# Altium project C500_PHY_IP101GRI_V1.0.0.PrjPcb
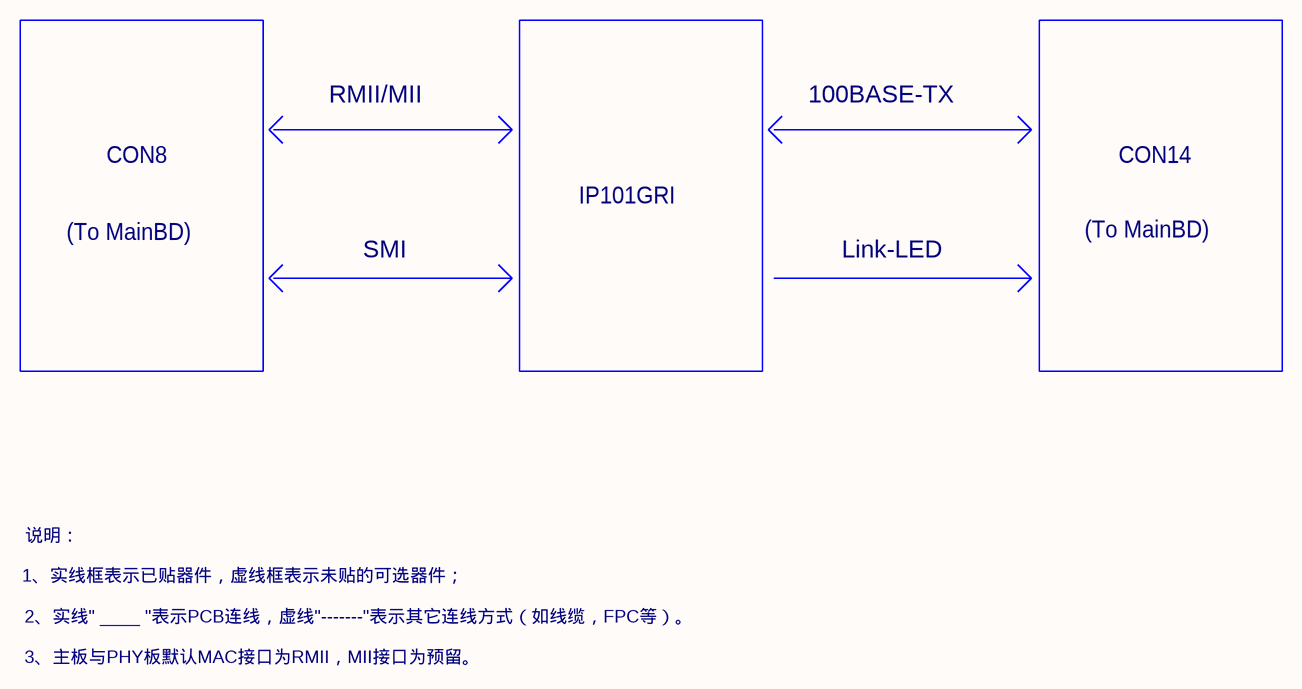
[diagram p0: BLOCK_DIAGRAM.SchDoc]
3 sheets, 70 parts. Net scope: flat (ports and power ports of the same name join across sheets).
Sheets:
  BLOCK_DIAGRAM.SchDoc
  INTERFACE.SchDoc
  IP101GRI.SchDoc

## Sheet BLOCK_DIAGRAM.SchDoc: C500_PHY_IP101GRI_PHY
size A3; Revision: V1.0.0; SheetNumber: 1; SheetTotal: 3; Release Date: 2019-05-28; SchModifyDate: 2019/5/28; PCBVersion: V1.0.0; PCBPartNumber: C500_PHY_IP101GRI_V1.0.0

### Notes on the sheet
- RMII/MII
- 100BASE-TX
- CON8
- CON14
- (To MainBD)
- SMI
- IP101GRI
- Link-LED
- 1、实线框表示已贴器件，虚线框表示未贴的可选器件；
- 说明：
- 2、实线" ____ "表示PCB连线，虚线"-------"表示其它连线方式（如线缆，FPC等）。
- 3、主板与PHY板默认MAC接口为RMII，MII接口为预留。

## Sheet INTERFACE.SchDoc: C500_PHY_IP101GRI_PHY
size A3; Revision: V1.0.0; SheetNumber: 2; SheetTotal: 3; Release Date: 2019-05-28; SchModifyDate: 2019/5/28; PCBVersion: V1.0.0; PCBPartNumber: C500_PHY_IP101GRI_V1.0.0
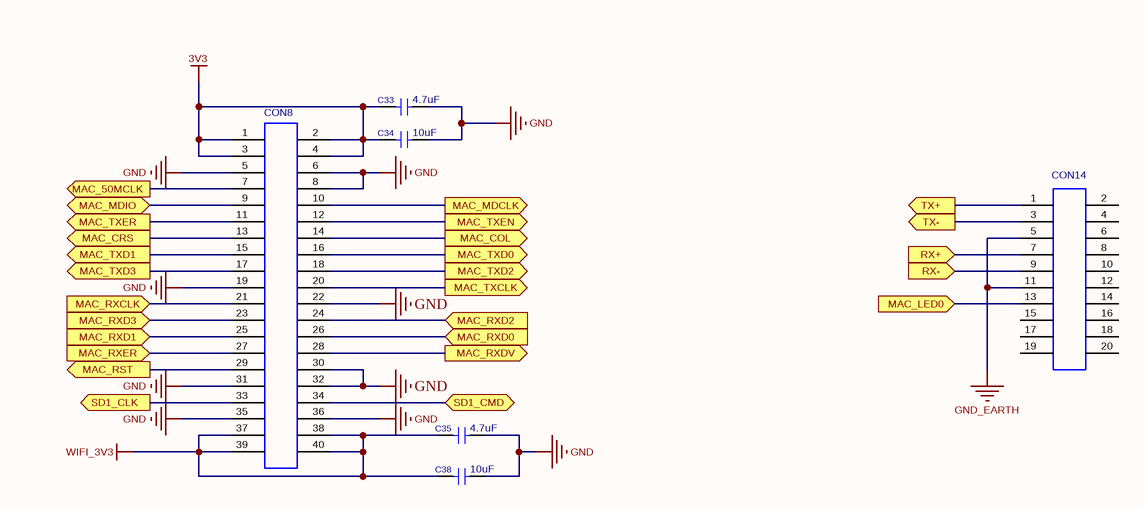
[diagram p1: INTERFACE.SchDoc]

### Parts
C33  4.7uF  [C0603]
C34  10uF  [C0805]
C35  4.7uF  [C0603]
C38  10uF  [C0805]
CON8  CON20X2_0MM5_BTB_DF12  [CON20X2_0MM5_BTB_DF12_N]  (value not drawn)
CON14  CON10X2_0MM5_BTB_DF12  [CON10X2_0MM5_BTB_DF12_N]  (value not drawn)

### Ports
MAC_50MCLK (out), MAC_COL (out), MAC_CRS (out), MAC_LED0 (in), MAC_MDCLK (out), MAC_MDIO (bidir), MAC_RST (out), MAC_RXCLK (in), MAC_RXD0 (in), MAC_RXD1 (in), MAC_RXD2 (in), MAC_RXD3 (in), MAC_RXDV (out), MAC_RXER (in), MAC_TXCLK (out), MAC_TXD0 (out), MAC_TXD1 (out), MAC_TXD2 (out), MAC_TXD3 (out), MAC_TXEN (out), MAC_TXER (out), RX+ (in), RX- (in), SD1_CLK (out), SD1_CMD (bidir), TX+ (out), TX- (out)

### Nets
3V3: C33.1 C34.1 CON8.1 CON8.2 CON8.3 CON8.4
GND: C33.2 C34.2 C35.2 C38.2 CON8.5 CON8.6 CON8.8 CON8.19 CON8.22 CON8.30 CON8.31 CON8.32 CON8.35 CON8.36
GND_EARTH: CON14.5 CON14.11
WIFI_3V3: C35.1 C38.1 CON8.37 CON8.38 CON8.39 CON8.40
MAC_50MCLK: CON8.7 ; port MAC_50MCLK
MAC_COL: CON8.14 ; port MAC_COL
MAC_CRS: CON8.13 ; port MAC_CRS
MAC_LED0: CON14.13 ; port MAC_LED0
MAC_MDCLK: CON8.10 ; port MAC_MDCLK
MAC_MDIO: CON8.9 ; port MAC_MDIO
MAC_RST: CON8.29 ; port MAC_RST
MAC_RXCLK: CON8.21 ; port MAC_RXCLK
MAC_RXD0: CON8.26 ; port MAC_RXD0
MAC_RXD1: CON8.25 ; port MAC_RXD1
MAC_RXD2: CON8.24 ; port MAC_RXD2
MAC_RXD3: CON8.23 ; port MAC_RXD3
MAC_RXDV: CON8.28 ; port MAC_RXDV
MAC_RXER: CON8.27 ; port MAC_RXER
MAC_TXCLK: CON8.20 ; port MAC_TXCLK
MAC_TXD0: CON8.16 ; port MAC_TXD0
MAC_TXD1: CON8.15 ; port MAC_TXD1
MAC_TXD2: CON8.18 ; port MAC_TXD2
MAC_TXD3: CON8.17 ; port MAC_TXD3
MAC_TXEN: CON8.12 ; port MAC_TXEN
RX+: CON14.7 ; port RX+
RX-: CON14.9 ; port RX-
TX+: CON14.1 ; port TX+
TX-: CON14.3 ; port TX-
NetCON8_11: CON8.11 ; port MAC_TXER
NetCON8_33: CON8.33 ; port SD1_CLK
NetCON8_34: CON8.34 ; port SD1_CMD

Not connected (* = marked no-connect by the designer): CON14 2 4 6 8 10 12 14 15 16 17 18 19 20

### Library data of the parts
C33 C35 = CC0304752XX: C/C,4.7uF,10V +/-10%,0603; Catalog: 陶瓷电容
C34 C38 = CC0501063XX: C/C,10uF,16V,+/-20%,0805; Catalog: 陶瓷电容
CON8 = CNBBM4000XX: 0.5mm ，BTB2*20Pin，SMT，公座，H3.0，DF12#(3.0)-40DS-0.5; PCB DECAL: CON20X2_0MM5_BTB_DF12_BOTTOM; Catalog: Connector
CON14 = CNBBM2000XX: 0.5mm ，BTB2*10Pin，SMT，公座，H3.0，DF12#(3.0)-20DS-0.5; PCB DECAL: CON10X2_0MM5_BTB_DF12_BOTTOM; Catalog: Connector

## Sheet IP101GRI.SchDoc: C500_PHY_IP101GRI_PHY
size A3; Revision: V1.0.0; SheetNumber: 3; SheetTotal: 3; Release Date: 2019-05-28; SchModifyDate: 2019/5/28; PCBVersion: V1.0.0; PCBPartNumber: C500_PHY_IP101GRI_V1.0.0
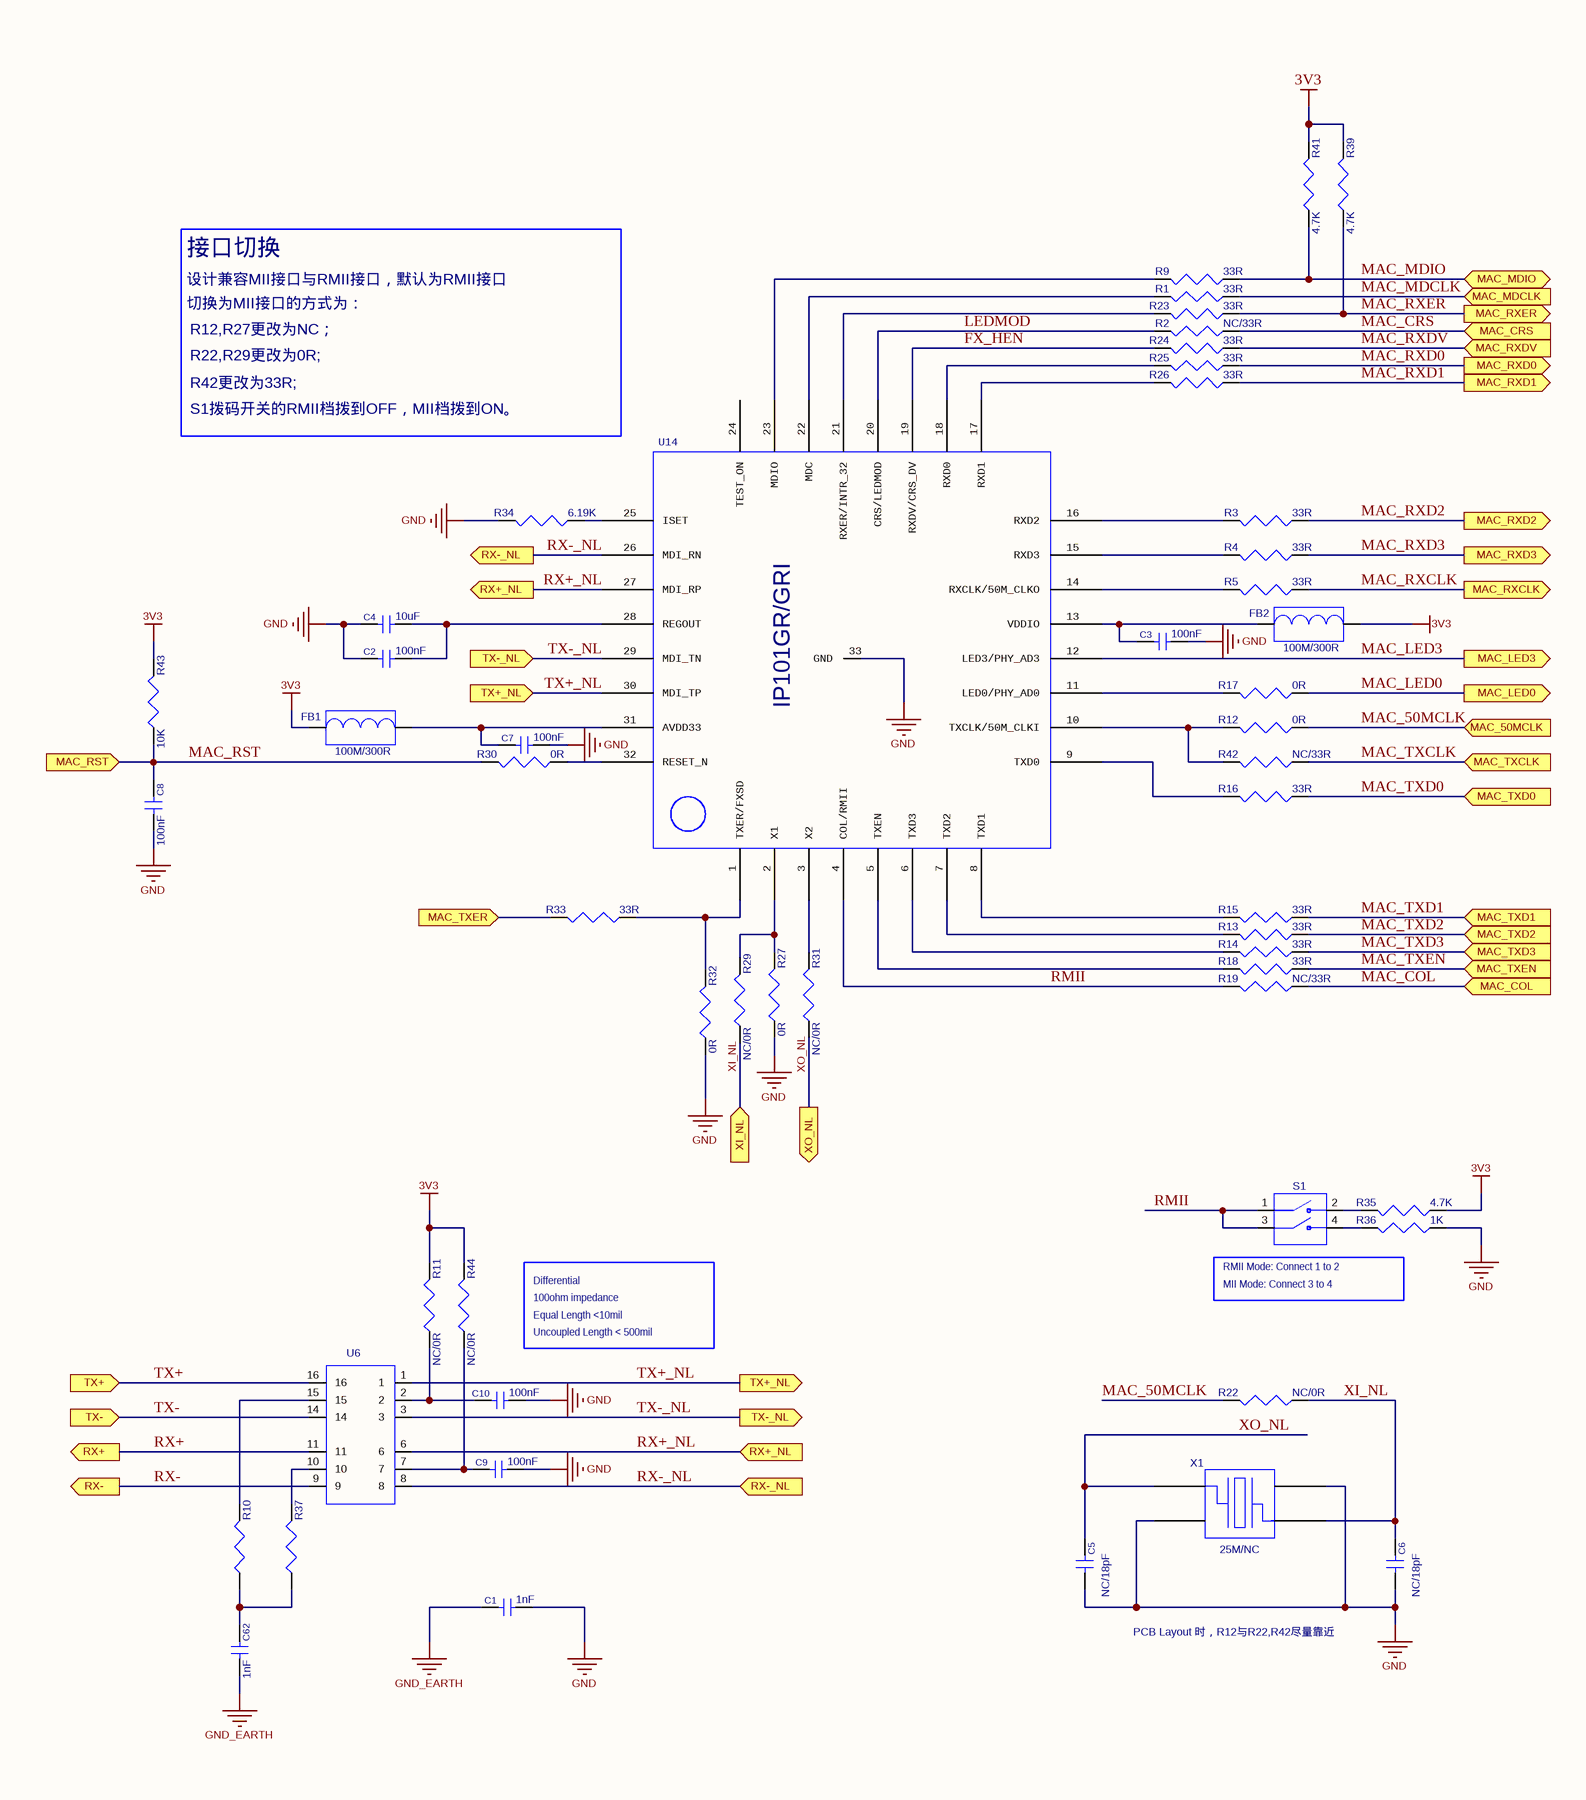
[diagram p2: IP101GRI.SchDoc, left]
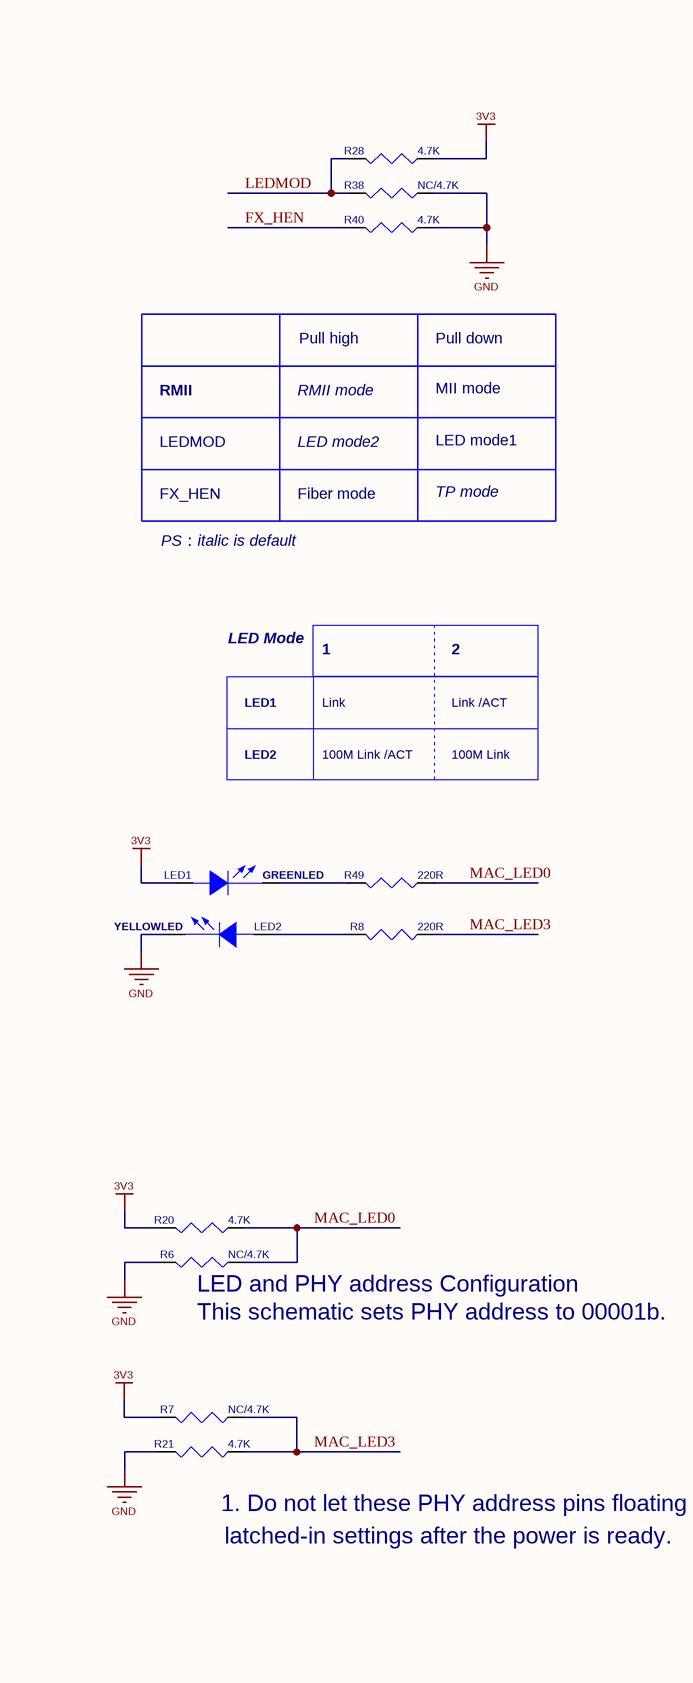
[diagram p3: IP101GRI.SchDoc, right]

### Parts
C1  1nF  [C1206]
C2  100nF  [C0603]
C3  100nF  [C0603]
C4  10uF  [C0603]
C5  NC/18pF  [C0603]
C6  NC/18pF  [C0603]
C7  100nF  [C0603]
C8  100nF  [C0603]
C9  100nF  [C0603]
C10  100nF  [C0603]
C62  1nF  [C1206]
FB1  100M/300R  [FB0603]
FB2  100M/300R  [FB0603]
LED1  GREENLED  [LED0603]
LED2  YELLOWLED  [LED0603]
R1  33R  [R0603]
R2  NC/33R  [R0603]
R3  33R  [R0603]
R4  33R  [R0603]
R5  33R  [R0603]
R6  NC/4.7K  [R0603]
R7  NC/4.7K  [R0603]
R8  220R  [R0603]
R9  33R  [R0603]
R10  75R  [R0603]  (value not drawn)
R11  NC/0R  [R0603]
R12  0R  [R0603]
R13  33R  [R0603]
R14  33R  [R0603]
R15  33R  [R0603]
R16  33R  [R0603]
R17  0R  [R0603]
R18  33R  [R0603]
R19  NC/33R  [R0603]
R20  4.7K  [R0603]
R21  4.7K  [R0603]
R22  NC/0R  [R0603]
R23  33R  [R0603]
R24  33R  [R0603]
R25  33R  [R0603]
R26  33R  [R0603]
R27  0R  [R0603]
R28  4.7K  [R0603]
R29  NC/0R  [R0603]
R30  0R  [R0603]
R31  NC/0R  [R0603]
R32  0R  [R0603]
R33  33R  [R0603]
R34  6.19K  [R0603]
R35  4.7K  [R0603]
R36  1K  [R0603]
R37  75R  [R0603]  (value not drawn)
R38  NC/4.7K  [R0603]
R39  4.7K  [R0603]
R40  4.7K  [R0603]
R41  4.7K  [R0603]
R42  NC/33R  [R0603]
R43  10K  [R0603]
R44  NC/0R  [R0603]
R49  220R  [R0603]
S1  SWITCH_DHM-02  [SWITCH_DHM-02_1MM27_5MM6X8MM3]  (value not drawn)
U6  TRC1102NLE  [TRC1102NLE]  (value not drawn)
U14  IP101GRI  [QFN32_0MM4_4X4MM]  (value not drawn)
X1  value 25M/NC  [KSX23]  (hidden comment: KSX23)

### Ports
MAC_50MCLK (in), MAC_COL (in), MAC_CRS (in), MAC_LED0 (out), MAC_LED3 (out), MAC_MDCLK (in), MAC_MDIO (bidir), MAC_RST (in), MAC_RXCLK (out), MAC_RXD0 (out), MAC_RXD1 (out), MAC_RXD2 (out), MAC_RXD3 (out), MAC_RXDV (in), MAC_RXER (out), MAC_TXCLK (in), MAC_TXD0 (in), MAC_TXD1 (in), MAC_TXD2 (in), MAC_TXD3 (in), MAC_TXEN (in), MAC_TXER (in), RX+ (out), RX+_NL (in), RX+_NL (out), RX- (out), RX-_NL (in), RX-_NL (out), TX+ (in), TX+_NL (in), TX+_NL (out), TX- (in), TX-_NL (in), TX-_NL (out), XI_NL (in), XO_NL (out)

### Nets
3V3: FB1.1 FB2.2 LED1.A R7.2 R11.2 R20.2 R28.1 R35.1 R39.2 R41.2 R43.2 R44.2
GND: C1.2 C2.1 C3.2 C4.1 C5.2 C6.2 C7.2 C8.2 C9.2 C10.2 LED2.K R6.2 R21.2 R27.1 R32.1 R34.2 R36.1 R38.1 R40.1 U14.33(GND) X1.2 X1.4
GND_EARTH: C1.1 C62.2
FX_HEN: R24.2 R40.2 U14.19(RXDV/CRS_DV)
LEDMOD: R2.2 R28.2 R38.2 U14.20(CRS/LEDMOD)
MAC_50MCLK: R12.1 R22.2 ; port MAC_50MCLK
MAC_COL: R19.1 ; port MAC_COL
MAC_CRS: R2.1 ; port MAC_CRS
MAC_LED0: R6.1 R17.1 R20.1 R49.1 ; port MAC_LED0
MAC_LED3: R7.1 R8.1 R21.1 U14.12(LED3/PHY_AD3) ; port MAC_LED3
MAC_MDCLK: R1.1 ; port MAC_MDCLK
MAC_MDIO: R9.1 R41.1 ; port MAC_MDIO
MAC_RST: C8.1 R30.2 R43.1 ; port MAC_RST
MAC_RXCLK: R5.1 ; port MAC_RXCLK
MAC_RXD0: R25.1 ; port MAC_RXD0
MAC_RXD1: R26.1 ; port MAC_RXD1
MAC_RXD2: R3.1 ; port MAC_RXD2
MAC_RXD3: R4.1 ; port MAC_RXD3
MAC_RXDV: R24.1 ; port MAC_RXDV
MAC_RXER: R23.1 R39.1 ; port MAC_RXER
MAC_TXCLK: R42.1 ; port MAC_TXCLK
MAC_TXD0: R16.1 ; port MAC_TXD0
MAC_TXD1: R15.1 ; port MAC_TXD1
MAC_TXD2: R13.1 ; port MAC_TXD2
MAC_TXD3: R14.1 ; port MAC_TXD3
MAC_TXEN: R18.1 ; port MAC_TXEN
RMII: R19.2 S1.1 S1.3 U14.4(COL/RMII)
RX+: U6.11 ; port RX+
RX+_NL: U6.6 U14.27(MDI_RP) ; port RX+_NL
RX-: U6.9 ; port RX-
RX-_NL: U6.8 U14.26(MDI_RN) ; port RX-_NL
TX+: U6.16 ; port TX+
TX+_NL: U6.1 U14.30(MDI_TP) ; port TX+_NL
TX-: U6.14 ; port TX-
TX-_NL: U6.3 U14.29(MDI_TN) ; port TX-_NL
XI_NL: C6.1 R22.1 R29.1 X1.1 ; port XI_NL
XO_NL: C5.1 R31.1 X1.3 ; port XO_NL
NetC2_2: C2.2 C4.2 U14.28(REGOUT)
NetC3_1: C3.1 FB2.1 U14.13(VDDIO)
NetC7_1: C7.1 FB1.2 U14.31(AVDD33)
NetC9_1: C9.1 R44.1 U6.7
NetC10_1: C10.1 R11.1 U6.2
NetC62_1: C62.1 R10.1 R37.1
NetCON8_11: R33.2 ; port MAC_TXER
NetLED1_K: LED1.K R49.2
NetLED2_A: LED2.A R8.2
NetR1_2: R1.2 U14.22(MDC)
NetR3_2: R3.2 U14.16(RXD2)
NetR4_2: R4.2 U14.15(RXD3)
NetR5_2: R5.2 U14.14(RXCLK/50M_CLKO)
NetR9_2: R9.2 U14.23(MDIO)
NetR10_2: R10.2 U6.15
NetR12_2: R12.2 R42.2 U14.10(TXCLK/50M_CLKI)
NetR13_2: R13.2 U14.7(TXD2)
NetR14_2: R14.2 U14.6(TXD3)
NetR15_2: R15.2 U14.8(TXD1)
NetR16_2: R16.2 U14.9(TXD0)
NetR17_2: R17.2 U14.11(LED0/PHY_AD0)
NetR18_2: R18.2 U14.5(TXEN)
NetR23_2: R23.2 U14.21(RXER/INTR_32)
NetR25_2: R25.2 U14.18(RXD0)
NetR26_2: R26.2 U14.17(RXD1)
NetR27_2: R27.2 R29.2 U14.2(X1)
NetR30_1: R30.1 U14.32(RESET_N)
NetR31_2: R31.2 U14.3(X2)
NetR32_2: R32.2 R33.1 U14.1(TXER/FXSD)
NetR34_1: R34.1 U14.25(ISET)
NetR35_2: R35.2 S1.2
NetR36_2: R36.2 S1.4
NetR37_2: R37.2 U6.10

Not connected (* = marked no-connect by the designer): U14 24(TEST_ON)

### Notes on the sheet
- 接口切换
- 设计兼容MII接口与RMII接口，默认为RMII接口
- 切换为MII接口的方式为：
- R12,R27更改为NC；
- R22,R29更改为0R;
- R42更改为33R;
- S1拨码开关的RMII档拨到OFF，MII档拨到ON。
- RMII
- RMII mode
- Pull high
- Pull down
- MII mode
- LEDMOD
- LED mode2
- LED mode1
- FX_HEN
- PS：italic is default
- Fiber mode
- TP mode
- LED Mode
- 1
- 2
- LED1
- Link
- Link /ACT
- LED2
- 100M Link /ACT
- 100M Link
- Differential
- MII Mode: Connect 3 to 4
- RMII Mode: Connect 1 to 2
- 100ohm impedance
- Uncoupled Length < 500mil
- Equal Length <10mil
- (near R6) LED and PHY address Configuration
- (near R6) This schematic sets PHY address to 00001b.
- (near R21) 1. Do not let these PHY address pins floating for the
- PCB Layout 时，R12与R22,R42尽量靠近
- latched-in settings after the power is ready.

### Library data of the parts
C1 C62 = CC0601021XX: C/C,1nF,2KV,+/-10%,1206; Catalog: 陶瓷电容
C2 C3 C7-C10 = CC0301040XX: C/C,100nF,25V,+/-5%,0603; Catalog: 陶瓷电容
C4 = CC0301061XX: C/C,10uF,25V,+/-20%,0603; Catalog: 陶瓷电容
C5 C6 = CC0301800XX: C/C,18pF,25V,+/-5%,0603; Remark: NC; Catalog: 陶瓷电容
FB1 FB2 = BE0303011XX: BEAD,300R,100MHz,0603; SOURCE_PATH: D:\PROGRAM FILES\ORCAD\ORCAD_10.5\TOOLS\CAPTURE\LIBRARY\DISCRETE.OLB; Catalog: 贴片磁珠
LED1 = LE03GXX00XX: GREENLED,0603; Catalog: 二极管
LED2 = LE03YXX00XX: YELLOW,LED0603; Catalog: 二极管
R1 R3-R5 R9 R13-R16 R18 R23-R26 R33 R42 = CR0333R00XX: Res,33R,1/10W,+/-1%,0603; Catalog: 贴片电阻
R2 R19 = CR0333R00XX: Res,33R,1/10W,+/-1%,0603; Remark: NC; Catalog: 贴片电阻
R6 R7 = CR0347010XX: Res,4.7K,1/10W,+/-1%,0603; Remark: NC; Catalog: 贴片电阻
R8 R49 = CR0302211XX: Res,220R,1/10W,+/-1%,0603; Catalog: 贴片电阻
R10 R37 = CR0375R00XX: Res,75R,1/10W,+/-1%,0603; Catalog: 贴片电阻
R11 R22 R29 R31 R44 = CR0300000XX: Res,0R,1/10W,+/-5%,0603; Remark: NC; Catalog: 贴片电阻
R12 R17 R27 R30 R32 = CR0300000XX: Res,0R,1/10W,+/-5%,0603; Catalog: 贴片电阻
R20 R21 R35 R39 R41 = CR0347010XX: Res,4.7K,1/10W,+/-1%,0603; Catalog: 贴片电阻
R28 R40 = CR0304720XX: Res,4.7K,1/10W,+/-5%,0603; Catalog: 贴片电阻
R34 = CR0361910XX: Res,6.19K,1/10W,+/-1%,0603; Catalog: 贴片电阻
R36 = CR0301020XX: Res,1K,1/10W,+/-5%,0603; Catalog: 贴片电阻
R38 = CR0304720XX: Res,4.7K,1/10W,+/-5%,0603; Remark: NC; Catalog: 贴片电阻
R43 = CR0310020XX: Res,10K,1/10W,+/-1%,0603; Catalog: 贴片电阻
S1 = SWSL04000XX: 开关,SlideSwitch,yimen,DHM-02,24V,1.27pitch,4pin; Catalog: Switch
U6 = TFSMD1601XX: Transformer,Trxcom,TRC1188NL,16pin; Part_RNEfNErNEncNE: NU704; room: ethernet; NC: 4,5,12,13; Source_Path: D:\MOBILE_PROJECT\WINCE\WINCE-7802\LIBRARY1.OLB; Catalog: 网络变压器
U14 = JCQFNPY01XX: PHY IC,IC PLUS,IP101GRI,QFN,32pin; Source_Path: F:\WORK_SPACE\ERIC\RTL8201\RTL8201F\SCHEMATIC\QFN32_RMII_MII\REFERENCE\V1.4\RTL8201F(E)_COLAY_REFERENCE_1.4.DSN; Value: RTL8201F-CG; PCB DECAL: IP101GR/GRI_QFN32_0MM4_4X4MM; Catalog: 集成电路
X1 = KSX23: Part_RNEfNErNEncNE: NY106; room: ak7801; Source_Path: L:\PCB_DESIGN_SYSTEM\ALLEGRO\LIB\SCHEMATIC\MISC.OLB

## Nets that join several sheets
3V3: INTERFACE (6 pins), IP101GRI (12 pins)
GND: INTERFACE (14 pins), IP101GRI (22 pins)
GND_EARTH: INTERFACE (CON14.5 CON14.11), IP101GRI (C1.1 C62.2)
MAC_50MCLK: INTERFACE (CON8.7), IP101GRI (R12.1 R22.2)
MAC_COL: INTERFACE (CON8.14), IP101GRI (R19.1)
MAC_CRS: INTERFACE (CON8.13), IP101GRI (R2.1)
MAC_LED0: INTERFACE (CON14.13), IP101GRI (R6.1 R17.1 R20.1 R49.1)
MAC_MDCLK: INTERFACE (CON8.10), IP101GRI (R1.1)
MAC_MDIO: INTERFACE (CON8.9), IP101GRI (R9.1 R41.1)
MAC_RST: INTERFACE (CON8.29), IP101GRI (C8.1 R30.2 R43.1)
MAC_RXCLK: INTERFACE (CON8.21), IP101GRI (R5.1)
MAC_RXD0: INTERFACE (CON8.26), IP101GRI (R25.1)
MAC_RXD1: INTERFACE (CON8.25), IP101GRI (R26.1)
MAC_RXD2: INTERFACE (CON8.24), IP101GRI (R3.1)
MAC_RXD3: INTERFACE (CON8.23), IP101GRI (R4.1)
MAC_RXDV: INTERFACE (CON8.28), IP101GRI (R24.1)
MAC_RXER: INTERFACE (CON8.27), IP101GRI (R23.1 R39.1)
MAC_TXCLK: INTERFACE (CON8.20), IP101GRI (R42.1)
MAC_TXD0: INTERFACE (CON8.16), IP101GRI (R16.1)
MAC_TXD1: INTERFACE (CON8.15), IP101GRI (R15.1)
MAC_TXD2: INTERFACE (CON8.18), IP101GRI (R13.1)
MAC_TXD3: INTERFACE (CON8.17), IP101GRI (R14.1)
MAC_TXEN: INTERFACE (CON8.12), IP101GRI (R18.1)
NetCON8_11: INTERFACE (CON8.11), IP101GRI (R33.2)
RX+: INTERFACE (CON14.7), IP101GRI (U6.11)
RX-: INTERFACE (CON14.9), IP101GRI (U6.9)
TX+: INTERFACE (CON14.1), IP101GRI (U6.16)
TX-: INTERFACE (CON14.3), IP101GRI (U6.14)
